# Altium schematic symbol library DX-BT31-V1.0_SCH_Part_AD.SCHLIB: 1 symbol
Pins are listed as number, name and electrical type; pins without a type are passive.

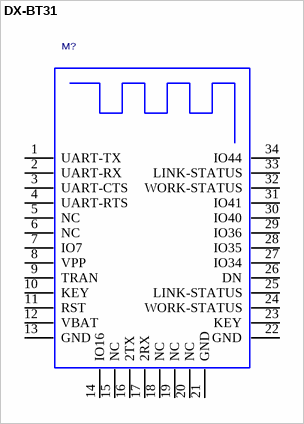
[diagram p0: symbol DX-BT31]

## DX-BT31
designator M?  (value not drawn)
PCB DECAL: DX-BT24
footprint DX-BT31
pins: 1 UART-TX, 2 UART-RX, 3 UART-CTS, 4 UART-RTS, 5 NC, 6 NC, 7 IO7, 8 VPP, 9 TRAN, 10 KEY, 11 RST, 12 VBAT, 13 GND, 14 IO16, 15 NC, 16 2TX, 17 2RX, 18 NC, 19 NC, 20 NC, 21 GND, 22 GND, 23 KEY, 24 WORK-STATUS, 25 LINK-STATUS, 26 DN, 27 IO34, 28 IO35, 29 IO36, 30 IO40, 31 IO41, 32 WORK-STATUS, 33 LINK-STATUS, 34 IO44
